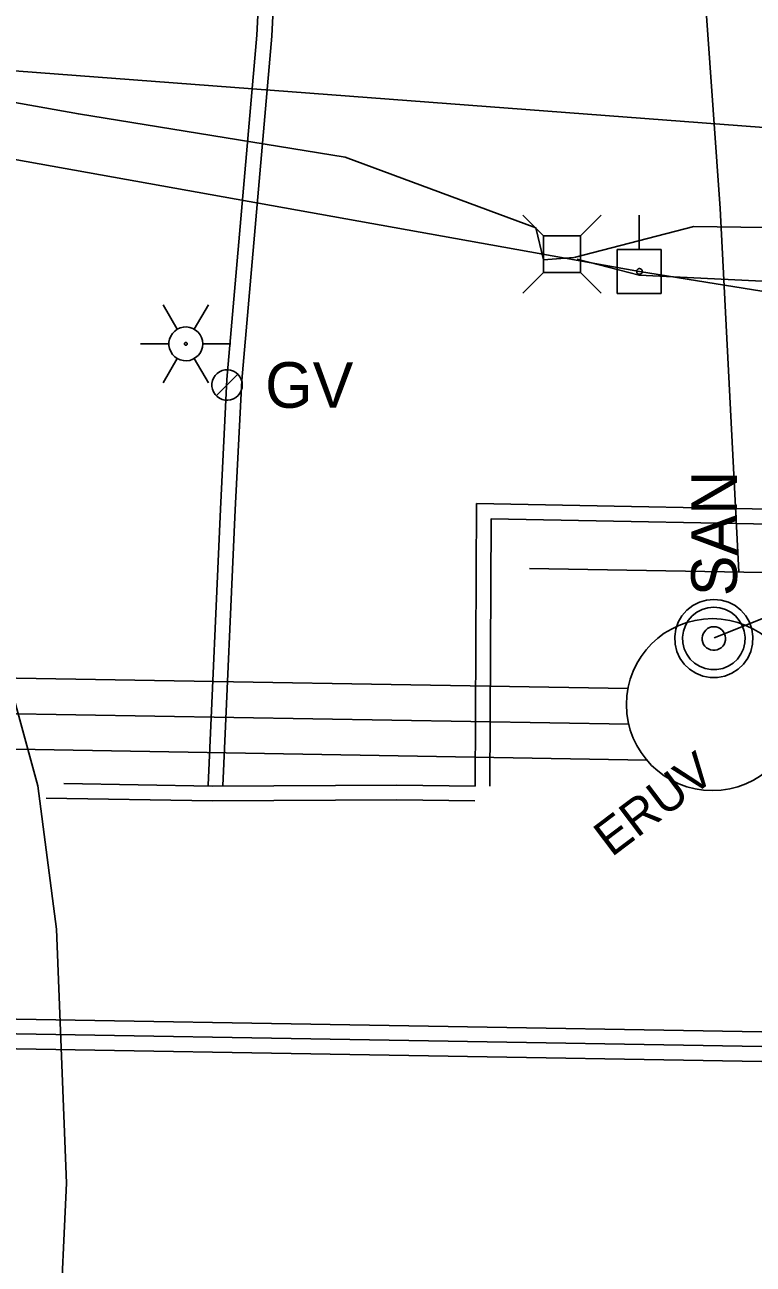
# Model space of a CAD drawing. Extents: x 596028 to 606371, y 330010 to 403088.
# Drawn here: x 604589.6 to 604651, y 337984.6 to 338089.1 of the extents above; entities that cross this region are included whole.
import ezdxf

# ---------------------------------------------------------------- set-up
doc = ezdxf.new("R2010")
doc.units = 0
for name, color, linetype in [('E_FTMS_Conduit', 7, 'Continuous'), ('E_LTG', 7, 'Continuous'), ('E_UTL_E_UG', 7, 'Continuous'), ('E_UTL_EPowerPole', 7, 'Continuous'), ('E_UTL_G', 7, 'Continuous'), ('E_UTL_G_UG', 7, 'Continuous'), ('E_UTL_Overhead', 7, 'Continuous'), ('E_UTL_SAN_MH', 7, 'Continuous'), ('E_UTL_SAN_UG_MMSD', 7, 'Continuous'), ('E_UTL_SAN_UG_OUTER_LIMITS', 7, 'Continuous'), ('E_UTL_T', 7, 'Continuous'), ('E_UTL_T_UG', 7, 'Continuous')]:
    doc.layers.add(name, color=color, linetype=linetype)

# ---------------------------------------------------------------- blocks, each defined once
blk = doc.blocks.new('ACAD_PROXY_ENTITY_15')
at = {"layer": 'E_LTG'}
for points in [[(1843663.8, 1030159.59), (1843660.17, 1030165.87)], [(1843668.16, 1030159.59), (1843671.79, 1030165.87)], [(1843670.34, 1030155.82), (1843670.26, 1030156.64), (1843670.02, 1030157.44), (1843669.64, 1030158.17), (1843669.13, 1030158.82), (1843668.51, 1030159.36), (1843667.79, 1030159.78), (1843667.01, 1030160.05), (1843666.19, 1030160.17), (1843665.36, 1030160.13), (1843664.56, 1030159.93), (1843663.8, 1030159.59), (1843663.13, 1030159.11), (1843662.56, 1030158.51), (1843662.11, 1030157.81), (1843661.8, 1030157.04), (1843661.64, 1030156.23), (1843661.64, 1030155.4), (1843661.8, 1030154.59), (1843662.11, 1030153.82), (1843662.56, 1030153.12), (1843663.13, 1030152.52), (1843663.8, 1030152.04), (1843664.56, 1030151.7), (1843665.36, 1030151.51), (1843666.19, 1030151.47), (1843667.01, 1030151.58), (1843667.79, 1030151.85), (1843668.51, 1030152.27), (1843669.13, 1030152.81), (1843669.64, 1030153.46), (1843670.02, 1030154.2), (1843670.26, 1030154.99), (1843670.34, 1030155.82)], [(1843670.34, 1030155.82), (1843670.26, 1030156.64), (1843670.02, 1030157.44), (1843669.64, 1030158.17), (1843669.13, 1030158.82), (1843668.51, 1030159.36), (1843667.79, 1030159.78), (1843667.01, 1030160.05), (1843666.19, 1030160.17), (1843665.36, 1030160.13), (1843664.56, 1030159.93), (1843663.8, 1030159.59), (1843663.13, 1030159.11), (1843662.56, 1030158.51), (1843662.11, 1030157.81), (1843661.8, 1030157.04), (1843661.64, 1030156.23), (1843661.64, 1030155.4), (1843661.8, 1030154.59), (1843662.11, 1030153.82), (1843662.56, 1030153.12), (1843663.13, 1030152.52), (1843663.8, 1030152.04), (1843664.56, 1030151.7), (1843665.36, 1030151.51), (1843666.19, 1030151.47), (1843667.01, 1030151.58), (1843667.79, 1030151.85), (1843668.51, 1030152.27), (1843669.13, 1030152.81), (1843669.64, 1030153.46), (1843670.02, 1030154.2), (1843670.26, 1030154.99), (1843670.34, 1030155.82)], [(1843670.34, 1030155.82), (1843670.26, 1030156.64), (1843670.02, 1030157.44), (1843669.64, 1030158.17), (1843669.13, 1030158.82), (1843668.51, 1030159.36), (1843667.79, 1030159.78), (1843667.01, 1030160.05), (1843666.19, 1030160.17), (1843665.36, 1030160.13), (1843664.56, 1030159.93), (1843663.8, 1030159.59), (1843663.13, 1030159.11), (1843662.56, 1030158.51), (1843662.11, 1030157.81), (1843661.8, 1030157.04), (1843661.64, 1030156.23), (1843661.64, 1030155.4), (1843661.8, 1030154.59), (1843662.11, 1030153.82), (1843662.56, 1030153.12), (1843663.13, 1030152.52), (1843663.8, 1030152.04), (1843664.56, 1030151.7), (1843665.36, 1030151.51), (1843666.19, 1030151.47), (1843667.01, 1030151.58), (1843667.79, 1030151.85), (1843668.51, 1030152.27), (1843669.13, 1030152.81), (1843669.64, 1030153.46), (1843670.02, 1030154.2), (1843670.26, 1030154.99), (1843670.34, 1030155.82)], [(1843654.37, 1030155.82), (1843661.62, 1030155.82)], [(1843666.34, 1030155.82), (1843666.34, 1030155.88), (1843666.32, 1030155.95), (1843666.29, 1030156.01), (1843666.24, 1030156.07), (1843666.19, 1030156.11), (1843666.13, 1030156.15), (1843666.07, 1030156.17), (1843666, 1030156.18), (1843665.93, 1030156.18), (1843665.86, 1030156.16), (1843665.8, 1030156.13), (1843665.74, 1030156.09), (1843665.69, 1030156.04), (1843665.66, 1030155.98), (1843665.63, 1030155.92), (1843665.62, 1030155.85), (1843665.62, 1030155.78), (1843665.63, 1030155.71), (1843665.66, 1030155.65), (1843665.69, 1030155.59), (1843665.74, 1030155.54), (1843665.8, 1030155.5), (1843665.86, 1030155.47), (1843665.93, 1030155.46), (1843666, 1030155.45), (1843666.07, 1030155.46), (1843666.13, 1030155.49), (1843666.19, 1030155.52), (1843666.24, 1030155.57), (1843666.29, 1030155.62), (1843666.32, 1030155.68), (1843666.34, 1030155.75), (1843666.34, 1030155.82)], [(1843670.34, 1030155.82), (1843677.59, 1030155.82)], [(1843660.17, 1030145.76), (1843663.8, 1030152.04)], [(1843671.79, 1030145.76), (1843668.16, 1030152.04)]]:
    blk.add_lwpolyline(points, dxfattribs=at)

msp = doc.modelspace()

# ---------------------------------------------------------------- linework, layer by layer
at = {"layer": 'E_FTMS_Conduit'}
msp.add_lwpolyline([(604586.79, 337850.4), (604597.83, 337855.35), (604594.44, 337908.62), (604593.95, 337938.1), (604592.48, 337978.69), (604593.09, 337991.4), (604592.23, 338012.83), (604590.67, 338024.91), (604588.22, 338033.89), (604584.13, 338043.61), (604549.18, 338095.05), (604541.85, 338114.6), (604525.21, 338159.57), (604492.18, 338224.83), (604485.27, 338243.18), (604482.26, 338261.55)], dxfattribs=at)
at = {"layer": 'E_UTL_E_UG'}
msp.add_lwpolyline([(604647.68, 338037.38), (604653.11, 338039.56), (604658.91, 338046.32), (604659.69, 338051.59)], dxfattribs=at)
at = {"layer": 'E_UTL_EPowerPole'}
for points in [[(604641.36, 338070.14), (604641.36, 338073.04)], [(604643.21, 338070.14), (604639.52, 338070.14)], [(604639.52, 338070.14), (604639.52, 338066.44)], [(604643.21, 338066.44), (604643.21, 338070.14)], [(604641.63, 338068.29), (604641.63, 338068.34), (604641.62, 338068.38), (604641.6, 338068.42), (604641.57, 338068.46), (604641.53, 338068.49), (604641.49, 338068.51), (604641.45, 338068.52), (604641.41, 338068.53), (604641.36, 338068.53), (604641.32, 338068.52), (604641.28, 338068.5), (604641.24, 338068.47), (604641.21, 338068.44), (604641.18, 338068.4), (604641.17, 338068.36), (604641.16, 338068.32), (604641.16, 338068.27), (604641.17, 338068.23), (604641.18, 338068.18), (604641.21, 338068.15), (604641.24, 338068.11), (604641.28, 338068.09), (604641.32, 338068.07), (604641.36, 338068.06), (604641.41, 338068.05), (604641.45, 338068.06), (604641.49, 338068.08), (604641.53, 338068.1), (604641.57, 338068.13), (604641.6, 338068.16), (604641.62, 338068.2), (604641.63, 338068.25), (604641.63, 338068.29)], [(604639.52, 338066.44), (604643.21, 338066.44)]]:
    msp.add_lwpolyline(points, dxfattribs=at)
at = {"layer": 'E_UTL_G'}
for points in [[(604607.9, 338058.71), (604607.88, 338058.96), (604607.81, 338059.19), (604607.7, 338059.41), (604607.55, 338059.6), (604607.37, 338059.76), (604607.15, 338059.88), (604606.92, 338059.96), (604606.68, 338060), (604606.44, 338059.98), (604606.2, 338059.93), (604605.98, 338059.83), (604605.78, 338059.68), (604605.61, 338059.51), (604605.48, 338059.3), (604605.39, 338059.08), (604605.34, 338058.84), (604605.34, 338058.59), (604605.39, 338058.35), (604605.48, 338058.13), (604605.61, 338057.92), (604605.78, 338057.74), (604605.98, 338057.6), (604606.2, 338057.5), (604606.44, 338057.44), (604606.68, 338057.43), (604606.92, 338057.47), (604607.15, 338057.55), (604607.37, 338057.67), (604607.55, 338057.83), (604607.7, 338058.02), (604607.81, 338058.24), (604607.88, 338058.47), (604607.9, 338058.71)], [(604605.71, 338057.81), (604607.53, 338059.62)]]:
    msp.add_lwpolyline(points, dxfattribs=at)
at = {"layer": 'E_UTL_G_UG'}
for points in [[(604605.02, 338024.97), (604606.06, 338048.24), (604606.61, 338059.17), (604609.14, 338088.22), (604611.15, 338128.29)], [(604606.27, 338024.92), (604607.31, 338048.18), (604607.86, 338059.09), (604610.39, 338088.14), (604612.4, 338128.23)], [(604649.78, 338042.95), (604648.19, 338073.59), (604646.14, 338102.57), (604646.77, 338128.75)], [(604592.86, 338025.1), (604605.4, 338024.88), (604620.94, 338024.97), (604627.53, 338024.88), (604627.66, 338048.71), (604659.6, 338048.1), (604660.29, 338024.5), (604661.98, 338024.48), (604678.08, 338023.1), (604703.11, 338023.01), (604728.65, 338022.61), (604754.62, 338022.17), (604788.4, 338021.61), (604836.01, 338021.58), (604864.95, 338021.48), (604896.37, 338021.5), (604900.27, 338026.31), (604935.52, 338026.84), (604967.49, 338026.3), (604985, 338025.85), (604984.37, 338049.04), (604985.32, 338080.05), (604985.44, 338110.91)], [(604628.78, 338024.89), (604628.9, 338047.44), (604658.38, 338046.87), (604659.04, 338024.47)], [(604632.12, 338043.25), (604936.03, 338038.05), (604984.53, 338043.23)], [(604591.38, 338023.88), (604605.39, 338023.63), (604620.94, 338023.72), (604627.51, 338023.65)]]:
    msp.add_lwpolyline(points, dxfattribs=at)
at = {"layer": 'E_UTL_Overhead'}
msp.add_lwpolyline([(604103.64, 338065.21), (604129.71, 338064.26), (604269.62, 338062.62), (604344.53, 338119.28), (604560.83, 338082.73), (604641.4, 338068.29), (604696.28, 338059.45), (604715.56, 338054.88), (604786.57, 338054.03), (604829.08, 338053.72), (604872.92, 338052.19), (604977.47, 338050.01), (605123.72, 338048.42), (605215.39, 338038.9)], dxfattribs=at)
at = {"layer": 'E_UTL_SAN_MH'}
for points in [[(604647.66, 338040.63), (604647.04, 338040.57), (604646.44, 338040.4), (604645.88, 338040.11), (604645.38, 338039.72), (604644.97, 338039.25), (604644.66, 338038.7), (604644.45, 338038.11), (604644.37, 338037.49), (604644.4, 338036.86), (604644.54, 338036.25), (604644.8, 338035.68), (604645.17, 338035.17), (604645.62, 338034.74), (604646.15, 338034.4), (604646.73, 338034.17), (604647.35, 338034.05), (604647.98, 338034.05), (604648.59, 338034.17), (604649.17, 338034.4), (604649.7, 338034.74), (604650.16, 338035.17), (604650.52, 338035.68), (604650.78, 338036.25), (604650.93, 338036.86), (604650.96, 338037.49), (604650.87, 338038.11), (604650.66, 338038.7), (604650.35, 338039.25), (604649.94, 338039.72), (604649.45, 338040.11), (604648.89, 338040.4), (604648.29, 338040.57), (604647.66, 338040.63)], [(604647.66, 338039.97), (604647.16, 338039.93), (604646.68, 338039.78), (604646.23, 338039.55), (604645.84, 338039.24), (604645.51, 338038.86), (604645.26, 338038.43), (604645.1, 338037.96), (604645.02, 338037.46), (604645.05, 338036.96), (604645.17, 338036.47), (604645.38, 338036.01), (604645.67, 338035.6), (604646.03, 338035.26), (604646.45, 338034.99), (604646.92, 338034.8), (604647.41, 338034.71), (604647.91, 338034.71), (604648.41, 338034.8), (604648.87, 338034.99), (604649.29, 338035.26), (604649.66, 338035.6), (604649.95, 338036.01), (604650.16, 338036.47), (604650.28, 338036.96), (604650.3, 338037.46), (604650.23, 338037.96), (604650.06, 338038.43), (604649.81, 338038.86), (604649.48, 338039.24), (604649.09, 338039.55), (604648.64, 338039.78), (604648.16, 338039.93), (604647.66, 338039.97)], [(604647.66, 338038.32), (604647.47, 338038.31), (604647.29, 338038.25), (604647.13, 338038.17), (604646.98, 338038.05), (604646.86, 338037.91), (604646.76, 338037.74), (604646.7, 338037.57), (604646.67, 338037.38), (604646.68, 338037.19), (604646.73, 338037.01), (604646.8, 338036.84), (604646.91, 338036.69), (604647.05, 338036.56), (604647.21, 338036.45), (604647.38, 338036.38), (604647.57, 338036.35), (604647.76, 338036.35), (604647.94, 338036.38), (604648.12, 338036.45), (604648.27, 338036.56), (604648.41, 338036.69), (604648.52, 338036.84), (604648.6, 338037.01), (604648.64, 338037.19), (604648.65, 338037.38), (604648.62, 338037.57), (604648.56, 338037.74), (604648.47, 338037.91), (604648.35, 338038.05), (604648.2, 338038.17), (604648.03, 338038.25), (604647.85, 338038.31), (604647.66, 338038.32)]]:
    msp.add_lwpolyline(points, dxfattribs=at)
msp.add_circle((604647.54, 338031.76), 7.25, dxfattribs=at)
at = {"layer": 'E_UTL_SAN_UG_MMSD'}
for p, q in [((604202.07, 338037.6), (604640.48, 338030.1)), ((603897.65, 338015.8), (604665.17, 338002.68))]:
    msp.add_line(p, q, dxfattribs=at)
at = {"layer": 'E_UTL_SAN_UG_OUTER_LIMITS'}
for p, q in [((604202.12, 338040.6), (604640.42, 338033.11)), ((604202.02, 338034.6), (604642, 338027.08)), ((603895.92, 338017.08), (604665.29, 338003.93)), ((603899.38, 338014.52), (604665.26, 338001.43))]:
    msp.add_line(p, q, dxfattribs=at)
at = {"layer": 'E_UTL_T'}
for points in [[(604633.31, 338071.3), (604631.56, 338073.05)], [(604636.41, 338071.3), (604638.16, 338073.05)], [(604636.41, 338071.3), (604633.31, 338071.3)], [(604633.31, 338071.3), (604633.31, 338068.2)], [(604636.41, 338068.2), (604636.41, 338071.3)], [(604633.31, 338068.2), (604631.56, 338066.45)], [(604633.31, 338068.2), (604636.41, 338068.2)], [(604636.41, 338068.2), (604638.16, 338066.45)]]:
    msp.add_lwpolyline(points, dxfattribs=at)
at = {"layer": 'E_UTL_T_UG'}
msp.add_line((604562.68, 338087.17), (604663.4, 338079.57), dxfattribs=at)
for points in [[(604562.68, 338087.17), (604594.09, 338081.58), (604616.58, 338077.92), (604632.65, 338071.98), (604633.31, 338069.27), (604635.85, 338069.47)], [(604635.88, 338069.46), (604645.97, 338072.07), (604665.75, 338071.79), (604675.98, 338071.72), (604686.22, 338071.65), (604691.3, 338070.77), (604693.7, 338065.09), (604696.28, 338059.45)], [(604636.13, 338069.34), (604641.36, 338067.97), (604659.25, 338067.1), (604661.02, 338063.19), (604660.82, 338055.93)]]:
    msp.add_lwpolyline(points, dxfattribs=at)

# ---------------------------------------------------------------- block references
at = {"layer": 'E_LTG', "xscale": 0.32808333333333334, "yscale": 0.32808333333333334}
msp.add_blockref('ACAD_PROXY_ENTITY_15', (-272.94, 85.23), dxfattribs=at)

# ---------------------------------------------------------------- texts
at = {"layer": 'E_UTL_G'}
msp.add_text('GV', height=3.85, dxfattribs=at).set_placement((604609.83, 338056.79))
at = {"layer": 'E_UTL_Overhead'}
msp.add_text('ERUV', height=3, rotation=37.1063, dxfattribs=at).set_placement((604639.04, 338018.85))
at = {"layer": 'E_UTL_SAN_MH'}
msp.add_text('SAN', height=3.849, rotation=90, dxfattribs=at).set_placement((604649.61, 338040.9))

doc.saveas('drawing.dxf')
